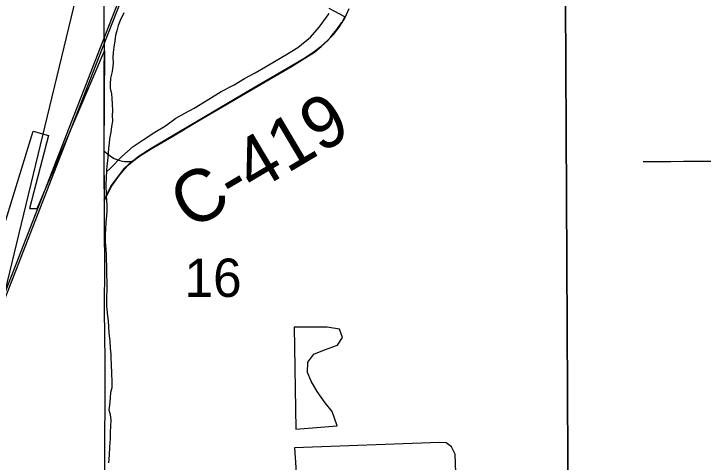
# Model space of a CAD drawing. Extents: x 0 to 34, y 0 to 22.
# Drawn here: x 19.665 to 20.417, y 11.815 to 12.305 of the extents above; entities that cross this region are included whole.
import ezdxf

# ---------------------------------------------------------------- set-up
doc = ezdxf.new("R2010")
doc.units = 0
for name, color, linetype in [('GM_X_Corporation', 7, 'Continuous'), ('GM_X_County_Road', 7, 'Continuous'), ('GM_X_County_Road_Text', 7, 'Continuous'), ('GM_X_Minor_Lake', 7, 'Continuous'), ('GM_X_Minor_River', 7, 'Continuous'), ('GM_X_Rail_Line', 7, 'Continuous'), ('GM_X_Section', 7, 'Continuous'), ('GM_X_Section_Text', 7, 'Continuous'), ('GM_X_Township_Road', 7, 'Continuous')]:
    doc.layers.add(name, color=color, linetype=linetype)

msp = doc.modelspace()

# ---------------------------------------------------------------- linework, layer by layer
at = {"layer": 'GM_X_Corporation'}
msp.add_lwpolyline([(19.62122, 11.9681), (19.68575, 12.17644), (19.70254, 12.17172), (19.68174, 12.09215), (19.68992, 12.09219), (19.76337, 12.26426), (19.76285, 12.15548), (19.76326, 12.10133), (19.77056, 12.11632), (19.78538, 12.1361), (19.79396, 12.14414), (19.79426, 12.14439), (19.80133, 12.14973), (19.81433, 12.15803), (19.83839, 12.17209), (19.86502, 12.18792), (19.92107, 12.22083), (19.96726, 12.24786), (19.98186, 12.25674), (19.99222, 12.26354), (19.99972, 12.26946), (20.00703, 12.27607), (20.01023, 12.27962), (20.01344, 12.28317), (20.01689, 12.28751), (20.01926, 12.29077), (20.02259, 12.29571), (20.02583, 12.30125), (20.00849, 12.31053)], dxfattribs=at)
at = {"layer": 'GM_X_County_Road'}
for points in [[(19.76316, 12.29475), (19.76316, 12.3009), (19.76321, 12.32276), (19.7636, 12.34774), (19.76345, 12.35999), (19.76402, 12.40996), (19.76379, 12.43184), (19.7639, 12.4537), (19.76396, 12.46891), (19.76401, 12.4796)], [(20.02558, 12.29991), (20.02604, 12.3007), (20.03032, 12.31065)], [(19.79417, 12.14359), (19.80154, 12.14918), (19.81454, 12.15748), (19.8386, 12.17155), (19.86523, 12.18737), (19.92128, 12.22029), (19.96747, 12.24731), (19.98207, 12.25619), (19.99244, 12.26299), (19.99994, 12.26891), (20.00724, 12.27552), (20.01044, 12.27907), (20.01365, 12.28262), (20.0171, 12.28697), (20.01947, 12.29022), (20.0228, 12.29516), (20.02558, 12.29991)], [(19.76358, 12.26371), (19.76347, 12.26898), (19.76324, 12.28772), (19.76316, 12.29475)], [(19.76306, 12.15493), (19.76317, 12.2097), (19.76315, 12.24398), (19.76358, 12.26371)], [(19.76347, 12.10078), (19.76301, 12.12562), (19.76306, 12.15493)], [(19.76306, 12.15493), (19.76838, 12.15066), (19.77102, 12.14853), (19.77387, 12.14685), (19.7769, 12.1455), (19.78004, 12.14445), (19.78327, 12.14373), (19.78557, 12.14352), (19.78954, 12.14335), (19.79417, 12.14359)], [(19.76347, 12.10078), (19.77077, 12.11577), (19.77424, 12.12105), (19.77967, 12.12845), (19.78559, 12.13556), (19.78954, 12.13979), (19.79417, 12.14359)], [(19.76514, 11.56177), (19.76468, 11.62219), (19.76453, 11.65628), (19.764, 11.72442), (19.76379, 11.75852), (19.76395, 11.80189), (19.76381, 11.82976), (19.76369, 11.85146), (19.76404, 11.87005), (19.76418, 11.92579), (19.76354, 11.98156), (19.76367, 12.03113), (19.7636, 12.06829), (19.76347, 12.10078)]]:
    msp.add_lwpolyline(points, dxfattribs=at)
at = {"layer": 'GM_X_Minor_Lake'}
for points in [[(19.97219, 11.85143), (20.01724, 11.8548), (20.01182, 11.87069), (20.00418, 11.88011), (19.99539, 11.89256), (19.98887, 11.90389), (19.98502, 11.91334), (19.98532, 11.92434), (19.9917, 11.93311), (20.00341, 11.93775), (20.01776, 11.94317), (20.02301, 11.95155), (20.01992, 11.96063), (20.00627, 11.9628), (19.97028, 11.96253)], [(19.97028, 11.96253), (19.97219, 11.85143)], [(19.97712, 11.73997), (20.14794, 11.74011), (20.15053, 11.74923), (20.15079, 11.7663), (20.14727, 11.78258), (20.14674, 11.80343), (20.14622, 11.82391), (20.142, 11.83222), (20.13629, 11.83635), (20.12909, 11.83668), (19.97081, 11.83094)], [(19.97081, 11.83094), (19.97712, 11.73997)]]:
    msp.add_lwpolyline(points, dxfattribs=at)
at = {"layer": 'GM_X_Minor_River'}
for points in [[(19.78463, 12.30574), (19.78056, 12.29733), (19.77835, 12.29198), (19.7769, 12.28626), (19.77544, 12.28131), (19.77476, 12.27522), (19.77371, 12.26837), (19.77303, 12.26228), (19.77272, 12.25696), (19.77279, 12.25088), (19.77177, 12.24175), (19.76996, 12.23451), (19.76966, 12.22843), (19.76973, 12.22349), (19.77095, 12.21743), (19.7714, 12.21212), (19.77185, 12.20605), (19.77233, 12.19883), (19.77201, 12.19389), (19.7721, 12.18744), (19.77103, 12.18173), (19.77035, 12.17564), (19.76892, 12.1684), (19.7686, 12.16346), (19.76791, 12.15813), (19.76761, 12.15243), (19.76657, 12.14406), (19.76588, 12.13873), (19.76557, 12.13341), (19.76529, 12.12581)], [(19.76553, 12.13239), (19.76949, 12.13586), (19.78228, 12.14885), (19.7947, 12.15994), (19.80564, 12.16723), (19.81846, 12.17567), (19.83015, 12.18258), (19.84146, 12.19063), (19.85126, 12.19639), (19.86145, 12.20178), (19.87729, 12.21138), (19.89087, 12.21982), (19.90483, 12.22713), (19.91615, 12.23404), (19.92785, 12.2402), (19.93916, 12.24673), (19.95085, 12.25365), (19.96142, 12.25979), (19.97424, 12.26785), (19.98817, 12.27933), (19.99757, 12.29002), (20.00845, 12.3049)], [(19.76529, 12.12581), (19.765, 12.11897), (19.76517, 12.10605), (19.76561, 12.10074), (19.76606, 12.09581), (19.76614, 12.08935), (19.76583, 12.08441), (19.76479, 12.0768), (19.7645, 12.06958), (19.76419, 12.06426), (19.7643, 12.0559), (19.76478, 12.04793), (19.76524, 12.04148), (19.76531, 12.03654), (19.76578, 12.02933), (19.76612, 12.00312), (19.76583, 11.99666), (19.76558, 11.98602), (19.76644, 11.97844), (19.76732, 11.96933), (19.76825, 11.95643), (19.76913, 11.94733), (19.76961, 11.93973), (19.77045, 11.93329), (19.77052, 11.92835), (19.77059, 11.92265), (19.77112, 11.91126), (19.77159, 11.90405), (19.77131, 11.89645), (19.76985, 11.8915), (19.76955, 11.88541), (19.76889, 11.87743), (19.7682, 11.87248), (19.76979, 11.86718), (19.77025, 11.86111), (19.76965, 11.84819), (19.76975, 11.84097), (19.7691, 11.83223), (19.76846, 11.8231), (19.76781, 11.81474)]]:
    msp.add_lwpolyline(points, dxfattribs=at)
at = {"layer": 'GM_X_Rail_Line'}
for points in [[(19.64053, 11.9641), (19.76166, 12.27455), (19.80366, 12.38242), (19.88252, 12.58389), (19.93765, 12.72439), (19.96249, 12.78907), (19.98233, 12.83962), (19.99409, 12.868), (20.00673, 12.89344), (20.02124, 12.92109), (20.03591, 12.94749)], [(19.64273, 11.96325), (19.76386, 12.2737), (19.80585, 12.38157), (19.88471, 12.58303), (19.93985, 12.72355), (19.96468, 12.78822), (19.98452, 12.83875), (19.99624, 12.86703), (20.00883, 12.89238), (20.02332, 12.91997), (20.03798, 12.94636)], [(18.77839, 9.17752), (18.7977, 9.24235), (18.81676, 9.33753), (18.92978, 9.89398), (18.99179, 10.21604), (19.01661, 10.33869), (19.04571, 10.42051), (19.10614, 10.57457), (19.35651, 11.20986), (19.49757, 11.57461), (19.62551, 11.88841), (19.64155, 11.94754), (19.80217, 12.61071)]]:
    msp.add_lwpolyline(points, dxfattribs=at)
at = {"layer": 'GM_X_Section'}
for points in [[(20.26496, 12.60488), (21.31252, 12.61292), (21.31182, 11.93487), (21.29872, 11.60315), (20.27005, 11.60623)], [(19.25603, 12.60125), (20.26496, 12.60488), (20.27005, 11.60623), (19.26987, 11.59924)]]:
    msp.add_lwpolyline(points, close=True, dxfattribs=at)
at = {"layer": 'GM_X_Township_Road'}
msp.add_lwpolyline([(20.3512, 12.14353), (20.3616, 12.14352), (20.38132, 12.14363), (20.39533, 12.14373), (20.40233, 12.14379), (20.40946, 12.14384), (20.42501, 12.14373), (20.43325, 12.14381), (20.43596, 12.14417), (20.43895, 12.14479), (20.4419, 12.14565), (20.44472, 12.14688), (20.44738, 12.14846), (20.44984, 12.15034), (20.45897, 12.15862), (20.46125, 12.16042), (20.46331, 12.16175), (20.47047, 12.16569)], dxfattribs=at)

# ---------------------------------------------------------------- texts
at = {"layer": 'GM_X_County_Road_Text'}
msp.add_text('C-419', height=0.056818, rotation=30.69218, dxfattribs=at).set_placement((19.85737, 12.06759))
at = {"layer": 'GM_X_Section_Text'}
msp.add_text('16', height=0.041856, rotation=0.00001, dxfattribs=at).set_placement((19.85081, 11.99567))

doc.saveas('drawing.dxf')
